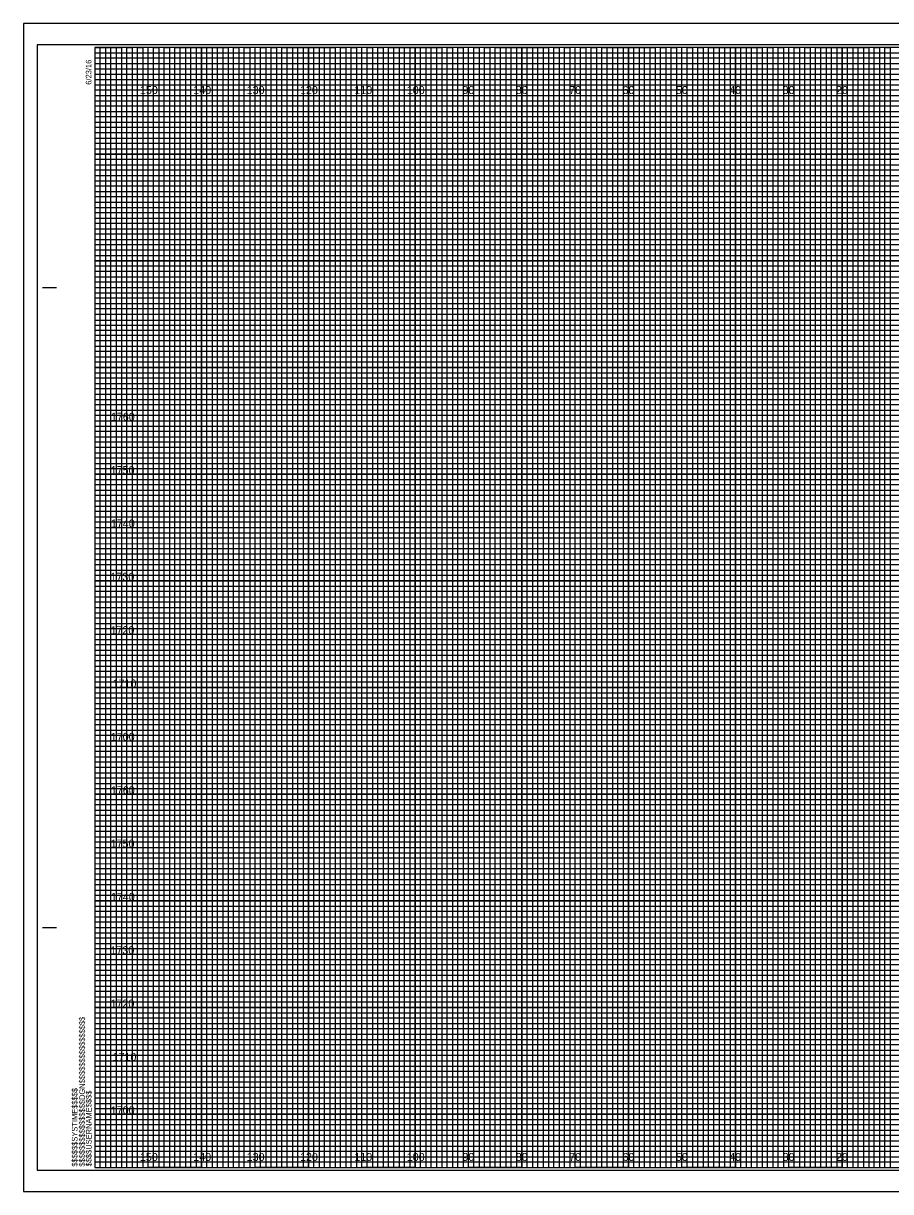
# Model space of a CAD drawing. Extents: x -15 to 323, y -5 to 6170.
# Drawn here: x -13.4 to 149.1, y 5715.5 to 5934.5 of the extents above; entities that cross this region are included whole.
import ezdxf

# ---------------------------------------------------------------- set-up
doc = ezdxf.new("R2010")
doc.units = 0
for name, color, linetype in [('Prop XS DDE', 7, 'Continuous'), ('Prop XS DDE Slope Text', 7, 'Continuous'), ('Prop XS DDE Text', 7, 'Continuous'), ('Prop XS Earthwork Shape', 7, 'Continuous'), ('Prop XS Noise Wall', 7, 'Continuous'), ('Prop XS Retaining Wall', 7, 'Continuous'), ('Prop XS Station Labels', 7, 'Continuous'), ('Scratch_Level_3', 7, 'Continuous'), ('Scratch_Level_7', 7, 'Continuous'), ('Scratch_Level_8', 7, 'Continuous'), ('Sheet Cross Section Grid Minor 1 CELL', 7, 'Continuous')]:
    doc.layers.add(name, color=color, linetype=linetype)

msp = doc.modelspace()

# ---------------------------------------------------------------- linework, layer by layer
at = {"layer": 'Prop XS DDE'}
msp.add_lwpolyline([(-13.4, 5715.5), (323.3, 5715.5), (323.3, 5934.5), (-13.4, 5934.5)], close=True, dxfattribs=at)
at = {"layer": 'Prop XS DDE Slope Text'}
msp.add_lwpolyline([(-10.8, 5719.5), (322.4, 5719.5), (322.4, 5930.5), (-10.8, 5930.5)], close=True, dxfattribs=at)
at = {"layer": 'Prop XS DDE Text'}
for p, q in [((10, 5720), (10, 5930)), ((20, 5720), (20, 5930)), ((30, 5720), (30, 5930)), ((40, 5720), (40, 5930)), ((50, 5720), (50, 5930)), ((60, 5720), (60, 5930)), ((70, 5720), (70, 5930)), ((80, 5720), (80, 5930)), ((90, 5720), (90, 5930)), ((100, 5720), (100, 5930)), ((110, 5720), (110, 5930)), ((120, 5720), (120, 5930)), ((130, 5720), (130, 5930)), ((140, 5720), (140, 5930)), ((0, 5920), (320, 5920)), ((0, 5910), (320, 5910)), ((0, 5900), (320, 5900)), ((0, 5890), (320, 5890)), ((0, 5880), (320, 5880)), ((0, 5870), (320, 5870)), ((0, 5860), (320, 5860)), ((0, 5850), (320, 5850)), ((0, 5840), (320, 5840)), ((0, 5830), (320, 5830)), ((0, 5820), (320, 5820)), ((0, 5810), (320, 5810)), ((0, 5800), (320, 5800)), ((0, 5790), (320, 5790)), ((0, 5780), (320, 5780)), ((0, 5770), (320, 5770)), ((0, 5760), (320, 5760)), ((0, 5750), (320, 5750)), ((0, 5740), (320, 5740)), ((0, 5730), (320, 5730))]:
    msp.add_line(p, q, dxfattribs=at)
at = {"layer": 'Prop XS Earthwork Shape'}
for p, q in [((10, 5930), (0, 5930)), ((10, 5720), (10, 5930)), ((30, 5930), (20, 5930)), ((20, 5930), (20, 5720)), ((30, 5720), (30, 5930)), ((50, 5930), (40, 5930)), ((40, 5930), (40, 5720)), ((50, 5720), (50, 5930)), ((70, 5930), (60, 5930)), ((60, 5930), (60, 5720)), ((70, 5720), (70, 5930)), ((90, 5930), (80, 5930)), ((80, 5930), (80, 5720)), ((90, 5720), (90, 5930)), ((110, 5930), (100, 5930)), ((100, 5930), (100, 5720)), ((110, 5720), (110, 5930)), ((130, 5930), (120, 5930)), ((120, 5930), (120, 5720)), ((130, 5720), (130, 5930)), ((150, 5930), (140, 5930)), ((140, 5930), (140, 5720)), ((20, 5720), (10, 5720)), ((40, 5720), (30, 5720)), ((60, 5720), (50, 5720)), ((80, 5720), (70, 5720)), ((100, 5720), (90, 5720)), ((120, 5720), (110, 5720)), ((140, 5720), (130, 5720))]:
    msp.add_line(p, q, dxfattribs=at)
for points in [[(0, 5920), (320, 5920), (320, 5910), (0, 5910)], [(0, 5900), (320, 5900), (320, 5890), (0, 5890)], [(0, 5880), (320, 5880), (320, 5870), (0, 5870)], [(0, 5860), (320, 5860), (320, 5850), (0, 5850)], [(0, 5840), (320, 5840), (320, 5830), (0, 5830)], [(0, 5820), (320, 5820), (320, 5810), (0, 5810)], [(0, 5800), (320, 5800), (320, 5790), (0, 5790)], [(0, 5780), (320, 5780), (320, 5770), (0, 5770)], [(0, 5760), (320, 5760), (320, 5750), (0, 5750)], [(0, 5740), (320, 5740), (320, 5730), (0, 5730)]]:
    msp.add_lwpolyline(points, dxfattribs=at)
at = {"layer": 'Prop XS Noise Wall'}
for p, q in [((-9.8, 5885), (-7.3, 5885)), ((-9.7, 5885), (-7.2, 5885)), ((-9.8, 5765), (-7.3, 5765)), ((-9.7, 5765), (-7.2, 5765)), ((0, 5720), (0, 5720)), ((0, 5720), (0, 5720)), ((0, 5720), (0, 5720)), ((0, 5720), (0, 5720)), ((0, 5720), (0, 5720)), ((0, 5720), (0, 5720)), ((0, 5720), (0, 5720))]:
    msp.add_line(p, q, dxfattribs=at)
msp.add_lwpolyline([(320, 5930), (0, 5930), (0, 5720), (320, 5720)], close=True, dxfattribs=at)
at = {"layer": 'Prop XS Retaining Wall'}
for points in [[(0, 5720), (1, 5720), (1, 5930), (2, 5930), (2, 5720)], [(2, 5720), (3, 5720), (3, 5930), (4, 5930), (4, 5720)], [(5, 5720), (6, 5720), (6, 5930), (7, 5930), (7, 5720)], [(7, 5720), (8, 5720), (8, 5930), (9, 5930), (9, 5720)], [(10, 5720), (11, 5720), (11, 5930), (12, 5930), (12, 5720)], [(12, 5720), (13, 5720), (13, 5930), (14, 5930), (14, 5720)], [(15, 5720), (16, 5720), (16, 5930), (17, 5930), (17, 5720)], [(17, 5720), (18, 5720), (18, 5930), (19, 5930), (19, 5720)], [(20, 5720), (21, 5720), (21, 5930), (22, 5930), (22, 5720)], [(22, 5720), (23, 5720), (23, 5930), (24, 5930), (24, 5720)], [(25, 5720), (26, 5720), (26, 5930), (27, 5930), (27, 5720)], [(27, 5720), (28, 5720), (28, 5930), (29, 5930), (29, 5720)], [(30, 5720), (31, 5720), (31, 5930), (32, 5930), (32, 5720)], [(32, 5720), (33, 5720), (33, 5930), (34, 5930), (34, 5720)], [(35, 5720), (36, 5720), (36, 5930), (37, 5930), (37, 5720)], [(37, 5720), (38, 5720), (38, 5930), (39, 5930), (39, 5720)], [(40, 5720), (41, 5720), (41, 5930), (42, 5930), (42, 5720)], [(42, 5720), (43, 5720), (43, 5930), (44, 5930), (44, 5720)], [(45, 5720), (46, 5720), (46, 5930), (47, 5930), (47, 5720)], [(47, 5720), (48, 5720), (48, 5930), (49, 5930), (49, 5720)], [(50, 5720), (51, 5720), (51, 5930), (52, 5930), (52, 5720)], [(52, 5720), (53, 5720), (53, 5930), (54, 5930), (54, 5720)], [(55, 5720), (56, 5720), (56, 5930), (57, 5930), (57, 5720)], [(57, 5720), (58, 5720), (58, 5930), (59, 5930), (59, 5720)], [(60, 5720), (61, 5720), (61, 5930), (62, 5930), (62, 5720)], [(62, 5720), (63, 5720), (63, 5930), (64, 5930), (64, 5720)], [(65, 5720), (66, 5720), (66, 5930), (67, 5930), (67, 5720)], [(67, 5720), (68, 5720), (68, 5930), (69, 5930), (69, 5720)], [(70, 5720), (71, 5720), (71, 5930), (72, 5930), (72, 5720)], [(72, 5720), (73, 5720), (73, 5930), (74, 5930), (74, 5720)], [(75, 5720), (76, 5720), (76, 5930), (77, 5930), (77, 5720)], [(77, 5720), (78, 5720), (78, 5930), (79, 5930), (79, 5720)], [(80, 5720), (81, 5720), (81, 5930), (82, 5930), (82, 5720)], [(82, 5720), (83, 5720), (83, 5930), (84, 5930), (84, 5720)], [(85, 5720), (86, 5720), (86, 5930), (87, 5930), (87, 5720)], [(87, 5720), (88, 5720), (88, 5930), (89, 5930), (89, 5720)], [(90, 5720), (91, 5720), (91, 5930), (92, 5930), (92, 5720)], [(92, 5720), (93, 5720), (93, 5930), (94, 5930), (94, 5720)], [(95, 5720), (96, 5720), (96, 5930), (97, 5930), (97, 5720)], [(97, 5720), (98, 5720), (98, 5930), (99, 5930), (99, 5720)], [(100, 5720), (101, 5720), (101, 5930), (102, 5930), (102, 5720)], [(102, 5720), (103, 5720), (103, 5930), (104, 5930), (104, 5720)], [(105, 5720), (106, 5720), (106, 5930), (107, 5930), (107, 5720)], [(107, 5720), (108, 5720), (108, 5930), (109, 5930), (109, 5720)], [(110, 5720), (111, 5720), (111, 5930), (112, 5930), (112, 5720)], [(112, 5720), (113, 5720), (113, 5930), (114, 5930), (114, 5720)], [(115, 5720), (116, 5720), (116, 5930), (117, 5930), (117, 5720)], [(117, 5720), (118, 5720), (118, 5930), (119, 5930), (119, 5720)], [(120, 5720), (121, 5720), (121, 5930), (122, 5930), (122, 5720)], [(122, 5720), (123, 5720), (123, 5930), (124, 5930), (124, 5720)], [(125, 5720), (126, 5720), (126, 5930), (127, 5930), (127, 5720)], [(127, 5720), (128, 5720), (128, 5930), (129, 5930), (129, 5720)], [(130, 5720), (131, 5720), (131, 5930), (132, 5930), (132, 5720)], [(132, 5720), (133, 5720), (133, 5930), (134, 5930), (134, 5720)], [(135, 5720), (136, 5720), (136, 5930), (137, 5930), (137, 5720)], [(137, 5720), (138, 5720), (138, 5930), (139, 5930), (139, 5720)], [(140, 5720), (141, 5720), (141, 5930), (142, 5930), (142, 5720)], [(142, 5720), (143, 5720), (143, 5930), (144, 5930), (144, 5720)], [(145, 5720), (146, 5720), (146, 5930), (147, 5930), (147, 5720)], [(147, 5720), (148, 5720), (148, 5930), (149, 5930), (149, 5720)]]:
    msp.add_lwpolyline(points, dxfattribs=at)
at = {"layer": 'Prop XS Station Labels'}
for points in [[(0, 5930), (5, 5930), (5, 5720), (15, 5720), (15, 5930), (25, 5930), (25, 5720), (35, 5720), (35, 5930), (45, 5930), (45, 5720), (55, 5720), (55, 5930), (65, 5930), (65, 5720), (75, 5720), (75, 5930), (85, 5930), (85, 5720), (95, 5720), (95, 5930), (105, 5930), (105, 5720), (115, 5720), (115, 5930), (125, 5930), (125, 5720), (135, 5720), (135, 5930), (145, 5930), (145, 5720), (155, 5720)], [(0, 5925), (275, 5925)], [(0, 5905), (320, 5905), (320, 5915), (0, 5915)], [(0, 5885), (320, 5885), (320, 5895), (0, 5895)], [(0, 5865), (320, 5865), (320, 5875), (0, 5875)], [(0, 5845), (320, 5845), (320, 5855), (0, 5855)], [(0, 5825), (320, 5825), (320, 5835), (0, 5835)], [(0, 5805), (320, 5805), (320, 5815), (0, 5815)], [(0, 5785), (320, 5785), (320, 5795), (0, 5795)], [(0, 5765), (320, 5765), (320, 5775), (0, 5775)], [(0, 5745), (320, 5745), (320, 5755), (0, 5755)], [(0, 5725), (320, 5725), (320, 5735), (0, 5735)]]:
    msp.add_lwpolyline(points, dxfattribs=at)
at = {"layer": 'Scratch_Level_7'}
for p, q in [((323.3, 5934.5), (-13.4, 5934.5)), ((-13.4, 5934.5), (-13.4, 5715.5)), ((-13.4, 5715.5), (323.3, 5715.5))]:
    msp.add_line(p, q, dxfattribs=at)
at = {"layer": 'Sheet Cross Section Grid Minor 1 CELL'}
for p, q in [((0, 5929), (260, 5929)), ((260, 5927.98), (0, 5927.98)), ((0, 5927.98), (0, 5927)), ((0, 5927), (260, 5927)), ((260, 5925.89), (0, 5925.89)), ((0, 5925.89), (0, 5924)), ((0, 5924), (320, 5924))]:
    msp.add_line(p, q, dxfattribs=at)
for points in [[(0, 5923), (270, 5923), (320, 5923), (320, 5922), (0, 5922)], [(0, 5921), (320, 5921), (320, 5919), (0, 5919)], [(0, 5918), (320, 5918), (320, 5917), (0, 5916.98)], [(0, 5916), (320, 5916), (320, 5914), (0, 5914)], [(0, 5913), (320, 5913), (320, 5912), (0, 5912)], [(0, 5911), (320, 5911), (320, 5909), (0, 5909)], [(0, 5908), (320, 5908), (320, 5907), (0, 5907)], [(0, 5906), (320, 5906), (320, 5904), (0, 5904)], [(0, 5903), (320, 5903), (320, 5902), (0, 5902)], [(0, 5901), (320, 5901), (320, 5899), (0, 5899)], [(0, 5898), (320, 5898), (320, 5897), (0, 5897)], [(0, 5896), (320, 5896), (320, 5893.95), (320, 5893), (320, 5892), (0, 5892)], [(0, 5894), (320, 5894), (320, 5893), (0, 5893)], [(0, 5891), (320, 5891), (320, 5889), (0, 5889.03)], [(0, 5889.03), (320, 5889), (320, 5888), (0, 5888)], [(0, 5887), (320, 5887), (320, 5886), (0, 5886)], [(0, 5884), (320, 5884), (320, 5883), (0, 5883)], [(0, 5882), (320, 5882), (320, 5881), (0, 5881)], [(-0.07, 5878.89), (320, 5878.89), (320, 5877.88), (-0.07, 5877.88)], [(0, 5877), (320, 5877), (320, 5876), (0, 5876)], [(0, 5874), (320, 5874), (320, 5873), (0, 5873)], [(0, 5872), (320, 5872), (320, 5871), (0, 5871)], [(0, 5869), (320, 5869), (320, 5868), (0, 5868)], [(0, 5867), (320, 5867), (320, 5866), (0, 5866)], [(0, 5864), (320, 5864), (320, 5863), (0, 5863)], [(0, 5862), (320, 5862), (320, 5861), (0, 5861)], [(0, 5859), (320, 5859), (319.99, 5857.98), (0, 5858)], [(0, 5857), (320, 5857), (320, 5856), (0, 5856)], [(0, 5854), (320, 5854), (320, 5853), (0, 5853)], [(0, 5852), (320, 5852), (320, 5851), (0, 5851)], [(0, 5849), (320, 5849), (320, 5848), (0, 5848)], [(0, 5847), (320, 5847), (320, 5846), (0, 5846)], [(0, 5844), (320, 5844), (320, 5843), (0, 5843)], [(0, 5842), (320, 5842), (320, 5841), (0, 5841)], [(0, 5839), (320, 5839), (320, 5838), (0, 5838)], [(0, 5836.99), (320.07, 5836.91), (320, 5836), (0, 5836)], [(0, 5834), (320, 5834), (320, 5833), (0, 5833)], [(0, 5832), (320, 5832), (320, 5831), (0, 5831)], [(0, 5829), (320, 5829), (320, 5828), (0, 5828)], [(0, 5827), (320, 5827), (320, 5826), (0, 5826)], [(0, 5824), (320, 5824), (320, 5823), (0, 5823)], [(0, 5822), (320, 5822), (320, 5821), (0, 5821)], [(0, 5819), (320, 5819), (320, 5818), (0, 5818)], [(0, 5817), (320, 5817), (320, 5816), (0, 5816)], [(0, 5814), (320, 5814), (320, 5813), (0, 5813)], [(0, 5812), (320, 5812), (320, 5811), (0, 5811)], [(0, 5809), (320, 5809), (320, 5808), (0, 5808)], [(0, 5807), (320, 5807), (320, 5806), (0, 5806)], [(0, 5804), (320, 5804), (320, 5803), (0, 5803)], [(0, 5802), (320, 5802), (320, 5801), (0, 5801)], [(0, 5799), (320, 5799), (319.99, 5797.98), (0, 5798)], [(0, 5797), (320, 5797), (320, 5796), (0, 5796)], [(0, 5794), (320, 5794), (320, 5793), (0, 5793)], [(0, 5792), (320, 5792), (320, 5791), (0, 5791)], [(0, 5789), (320, 5789), (320, 5788), (0, 5788)], [(0, 5787), (320, 5787), (320, 5786), (0, 5786)], [(0, 5784), (320, 5784), (320, 5783), (0, 5783)], [(0, 5782), (320, 5782), (320, 5781), (0, 5781)], [(0, 5779), (320, 5779), (320, 5778), (0, 5778)], [(0, 5776.99), (320.07, 5776.91), (320, 5776), (0, 5776)], [(0, 5774), (320, 5774), (320, 5773), (0, 5773)], [(0, 5772), (320, 5772), (320, 5771), (0, 5771)], [(0, 5769), (320, 5769), (320, 5768), (0, 5768)], [(0, 5767), (320, 5767), (320, 5766), (0, 5766)], [(0, 5764), (320, 5764), (320, 5763), (0, 5763)], [(0, 5762), (320, 5762), (320, 5761), (0, 5761)], [(0, 5759), (320, 5759), (320, 5758), (0, 5758)], [(0, 5757), (320, 5757), (320, 5756), (0, 5756)], [(0, 5754), (320, 5754), (320, 5753), (0, 5753)], [(0, 5752), (320, 5752), (320, 5751), (0, 5751)], [(0, 5749), (320, 5749), (320, 5748), (0, 5748)], [(0, 5747), (320, 5747), (320, 5746), (0, 5746)], [(0, 5744), (320, 5744), (320, 5743), (0, 5743)], [(0, 5742), (320, 5742), (320, 5741), (0, 5741)], [(0, 5739), (320, 5739), (320, 5738), (0, 5738)], [(0, 5737), (320, 5737), (320, 5736), (0, 5736)], [(0, 5734), (320, 5734), (320, 5733), (0, 5733)], [(0, 5732), (320, 5732), (320, 5731), (0, 5731)], [(0, 5729), (320, 5729), (320, 5728), (0, 5728)], [(0, 5727), (320, 5727), (320, 5726), (0, 5726)], [(0, 5724), (320, 5724), (320, 5723), (0, 5723)], [(0, 5722), (320, 5722), (320, 5721), (0, 5721)]]:
    msp.add_lwpolyline(points, dxfattribs=at)

# ---------------------------------------------------------------- texts
at = {"layer": 'Prop XS Noise Wall'}
for s, p in [('6/23/16', (-0.65, 5923)), ('$$$$$$$$$$$$$$$$DGN$$$$$$$$$$$$$$$$', (-1.88, 5720.18)), ('$$$$$$SYSTIME$$$$$', (-3.26, 5720.18)), ('$$$$USERNAME$$$$', (-0.62, 5720.23))]:
    msp.add_text(s, height=1.05, rotation=90, dxfattribs=at).set_placement(p)
at = {"layer": 'Scratch_Level_3'}
for s, p in [('1760', (3, 5860)), ('1750', (2.96, 5850)), ('1740', (3, 5840)), ('1730', (2.92, 5830)), ('1720', (2.93, 5820)), ('1710', (3.31, 5810)), ('1700', (2.98, 5800)), ('1760', (3, 5790)), ('1750', (2.96, 5780)), ('1740', (3, 5770)), ('1730', (2.92, 5760)), ('1720', (2.93, 5750)), ('1710', (3.31, 5740)), ('1700', (2.98, 5730))]:
    msp.add_text(s, height=1.5, dxfattribs=at).set_placement(p)
at = {"layer": 'Scratch_Level_8'}
for s, p in [('150', (8.44, 5921.25)), ('140', (18.44, 5921.25)), ('130', (28.44, 5921.25)), ('120', (38.44, 5921.25)), ('110', (48.62, 5921.25)), ('100', (58.44, 5921.25)), ('90', (68.86, 5921.25)), ('80', (78.86, 5921.25)), ('70', (88.86, 5921.25)), ('60', (98.86, 5921.25)), ('50', (108.86, 5921.25)), ('40', (118.86, 5921.25)), ('30', (128.86, 5921.25)), ('20', (138.86, 5921.25)), ('150', (8.44, 5721.25)), ('140', (18.44, 5721.25)), ('130', (28.44, 5721.25)), ('120', (38.44, 5721.25)), ('110', (48.62, 5721.25)), ('100', (58.44, 5721.25)), ('90', (68.86, 5721.25)), ('80', (78.86, 5721.25)), ('70', (88.86, 5721.25)), ('60', (98.86, 5721.25)), ('50', (108.86, 5721.25)), ('40', (118.86, 5721.25)), ('30', (128.86, 5721.25)), ('20', (138.86, 5721.25))]:
    msp.add_text(s, height=1.5, dxfattribs=at).set_placement(p)

doc.saveas('drawing.dxf')
